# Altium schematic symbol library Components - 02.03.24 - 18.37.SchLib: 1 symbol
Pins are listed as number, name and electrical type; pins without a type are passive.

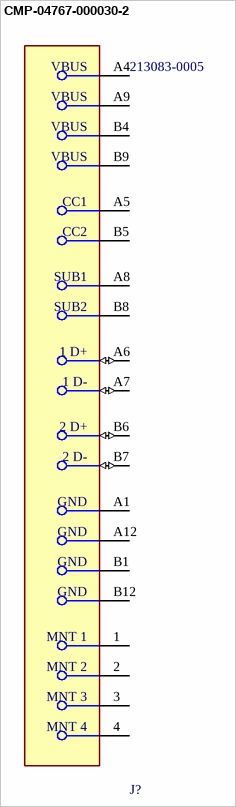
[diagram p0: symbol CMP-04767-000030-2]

## CMP-04767-000030-2
designator J?, comment 213083-0005
CONN RCP USB2.0 TYP C 24P SMD RA; NexarPartId: 114105384; Current Rating: 5A; Number of Contacts: 16; Voltage Rating: 30V; Gender: Receptacle
footprint FP-2130830005-MFG
pins: 1 MNT 1, 2 MNT 2, 3 MNT 3, 4 MNT 4, A1 GND (power), A4 VBUS (power), A5 CC1, A6 1 D+ (io), A7 1 D- (io), A8 SUB1, A9 VBUS (power), A12 GND (power), B1 GND (power), B4 VBUS (power), B5 CC2, B6 2 D+ (io), B7 2 D- (io), B8 SUB2, B9 VBUS (power), B12 GND (power)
